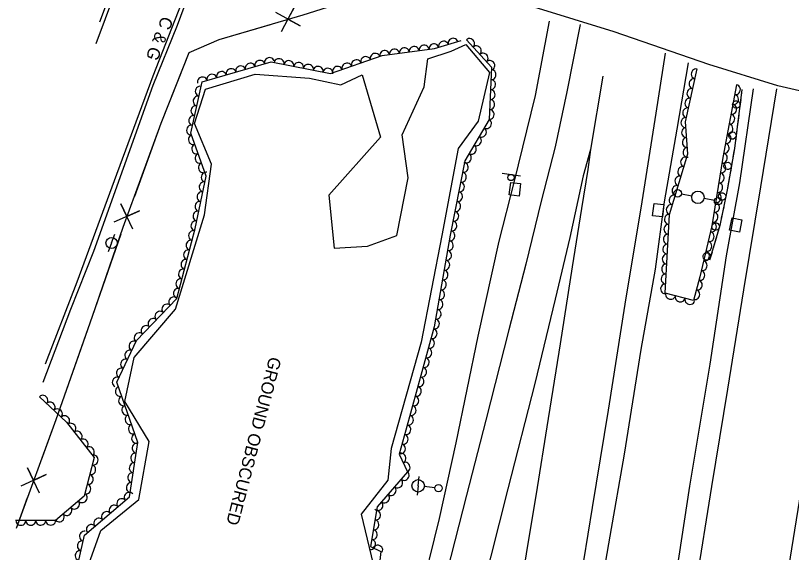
# Model space of a CAD drawing. Extents: x 1722896 to 1754269, y 648279 to 666297.
# Drawn here: x 1725426.2 to 1725737.8, y 659590.4 to 659806.2 of the extents above; entities that cross this region are included whole.
import ezdxf

# ---------------------------------------------------------------- set-up
doc = ezdxf.new("R2010")
doc.units = 0
for name, color, linetype in [('DESIGN - CENTERLINE - Proposed', 7, 'Continuous'), ('DESIGN - CENTERLINE - Proposed Text', 7, 'Continuous'), ('DESIGN - PUBLIC HEARING - Shapes', 7, 'Continuous'), ('DESIGN - SCRATCH - User 1', 7, 'Continuous'), ('SURVEY - CENTERLINE - Preliminary', 7, 'Continuous'), ('SURVEY - CENTERLINE - Preliminary Text', 7, 'Continuous'), ('SURVEY - DRAINAGE - Natural Features', 7, 'Continuous'), ('SURVEY - DTM - Breaklines', 7, 'Continuous'), ('SURVEY - VEGETATION - Features with Text', 7, 'Continuous')]:
    doc.layers.add(name, color=color, linetype=linetype)

msp = doc.modelspace()

# ---------------------------------------------------------------- linework, layer by layer
at = {"layer": 'DESIGN - CENTERLINE - Proposed'}
msp.add_lwpolyline([(1725873.4, 659822.69), (1725871.84, 659814.34), (1725866.25, 659775.49), (1725864.61, 659769.04), (1725840.89, 659767.23), (1725811.36, 659766.56), (1725786.34, 659767.74), (1725753.72, 659772.97), (1725732.26, 659777.9), (1725704.65, 659786.55), (1725666.54, 659799.64), (1725616.61, 659815.21), (1725586.06, 659824.9), (1725587.44, 659831.41), (1725593.62, 659870.36), (1725595.34, 659877.02)], dxfattribs=at)
at = {"layer": 'DESIGN - CENTERLINE - Proposed Text'}
for points in [[(1725591.57, 659822.25), (1725541.53, 659806.35), (1725507.88, 659796.45), (1725495.73, 659791.23), (1725484.59, 659762.77), (1725469.34, 659721.04), (1725456.93, 659685.27), (1725442.38, 659643.72), (1725426.43, 659600.07)], [(1725532.95, 659799.76), (1725538.27, 659809.67), (1725535.56, 659804.7), (1725540.53, 659801.99), (1725530.69, 659807.44)], [(1725528.49, 659802.52), (1725507.88, 659796.45), (1725495.73, 659791.23), (1725491.47, 659780.35)], [(1725491.47, 659780.35), (1725484.59, 659762.77), (1725473.91, 659733.54)], [(1725473.25, 659720.36), (1725468.44, 659730.53), (1725470.83, 659725.4), (1725475.96, 659727.78), (1725465.73, 659723.11)], [(1725468.43, 659718.4), (1725456.93, 659685.27), (1725453.18, 659674.58)], [(1725453.18, 659674.58), (1725442.38, 659643.72), (1725436.44, 659627.46)], [(1725435.77, 659614.29), (1725430.97, 659624.46), (1725433.35, 659619.33), (1725438.49, 659621.71), (1725428.26, 659617.04)], [(1725430.91, 659612.34), (1725426.43, 659600.07)]]:
    msp.add_lwpolyline(points, dxfattribs=at)
at = {"layer": 'DESIGN - PUBLIC HEARING - Shapes'}
msp.add_line((1725621.62, 659742.89), (1725629.03, 659741.74), dxfattribs=at)
msp.add_circle((1725625.16, 659741.1), 1.25, dxfattribs=at)
at = {"layer": 'DESIGN - SCRATCH - User 1'}
for points in [[(1725717.91, 659776.41), (1725714.9, 659752.76), (1725712.14, 659736.83), (1725709.02, 659721.78), (1725704.91, 659707.83)], [(1725717.91, 659776.41), (1725717.61, 659774.08)], [(1725717.41, 659772.49), (1725716.83, 659767.93)], [(1725716.33, 659764.01), (1725716.04, 659761.68)], [(1725716.63, 659766.34), (1725716.33, 659764.01)], [(1725715.83, 659760.09), (1725715.26, 659755.53)], [(1725714.71, 659751.62), (1725714.3, 659749.3)], [(1725715.05, 659753.94), (1725714.9, 659752.76), (1725714.71, 659751.62)], [(1725714.03, 659747.73), (1725713.25, 659743.19)], [(1725712.57, 659739.3), (1725712.17, 659736.99)], [(1725712.97, 659741.62), (1725712.57, 659739.3)], [(1725711.85, 659735.42), (1725710.91, 659730.92)], [(1725710.11, 659727.05), (1725709.63, 659724.75)], [(1725710.59, 659729.35), (1725710.11, 659727.05)], [(1725709.31, 659723.18), (1725709.02, 659721.78), (1725708.12, 659718.74)], [(1725707.67, 659717.2), (1725707.01, 659714.95)], [(1725707.01, 659714.95), (1725706.34, 659712.7)], [(1725705.89, 659711.16), (1725704.91, 659707.83)]]:
    msp.add_lwpolyline(points, dxfattribs=at)
for centre, start, end in [((1725715.64, 659770.42), 106.0198, 106.0099), ((1725714.06, 659758.02), 106.0198, 106.0099), ((1725712.16, 659745.74), 103.4291, 103.4193), ((1725709.92, 659733.49), 101.5223, 101.5124), ((1725707.34, 659721.39), 96.8781, 96.8683), ((1725703.81, 659709.4), 96.8781, 96.8683)]:
    msp.add_arc(centre, 1.5, start, end, dxfattribs=at)
at = {"layer": 'SURVEY - CENTERLINE - Preliminary'}
for points in [[(1725452.97, 659578.29), (1725460.4, 659599.26), (1725475.66, 659611.68), (1725479.85, 659635.04), (1725470.12, 659651.09), (1725473.88, 659668.78), (1725490.45, 659688.16), (1725502.05, 659726.06), (1725504.83, 659746.44), (1725498.09, 659762.81), (1725502.49, 659776.59), (1725522.38, 659782.63), (1725544.18, 659780.97), (1725556.82, 659778.3), (1725565.39, 659782.42), (1725572.7, 659757.38), (1725552.02, 659734.04), (1725554.2, 659712.66), (1725567.55, 659713.46), (1725579.38, 659717.85), (1725583.9, 659740.93), (1725581.42, 659758.21), (1725590.29, 659777.53), (1725591.79, 659788.8), (1725601.15, 659791.84), (1725607, 659794.61)], [(1725607, 659794.61), (1725616.48, 659783.36), (1725612, 659763.76), (1725603.94, 659752.8), (1725597.41, 659717.82), (1725589.03, 659674.93), (1725577.08, 659632.19), (1725575.73, 659619.48), (1725565.06, 659605.84), (1725569.84, 659585.79)]]:
    msp.add_lwpolyline(points, dxfattribs=at)
at = {"layer": 'SURVEY - CENTERLINE - Preliminary Text'}
for points in [[(1725475.25, 659877.21), (1725479.16, 659873.75), (1725481.44, 659870.6), (1725483.2, 659865.75), (1725483.33, 659861.83), (1725482.61, 659857.42), (1725479.69, 659850.19), (1725472.45, 659831.99), (1725465.99, 659815.01), (1725458.48, 659794.83)], [(1725474.48, 659875.7), (1725477.04, 659873.79), (1725479.42, 659871.22), (1725480.89, 659868.09), (1725481.79, 659863.63), (1725481.25, 659857.67), (1725476.85, 659847.43), (1725468.91, 659827.5), (1725459.9, 659803.51)], [(1725586.72, 659832.95), (1725561.03, 659841.8), (1725539.85, 659849.35), (1725530.51, 659852.94), (1725525.68, 659854.1), (1725520.16, 659853.9), (1725514.36, 659852.01), (1725509.77, 659849.09), (1725506.48, 659845.71), (1725502.63, 659838.48), (1725492.72, 659810.96), (1725481.27, 659781.84), (1725465.74, 659739.73), (1725450.86, 659699.09), (1725438.04, 659666.13)], [(1725586.35, 659831.55), (1725556.04, 659841.25), (1725547.17, 659844.96), (1725537.97, 659848.28), (1725529.75, 659851.86), (1725524.54, 659852.8), (1725518.49, 659852.08), (1725513.81, 659849.69), (1725509.63, 659846.2), (1725506.42, 659842.05), (1725504.57, 659838.39), (1725499.07, 659824.01), (1725491.15, 659802.17), (1725481.36, 659778.09), (1725457.53, 659711.43), (1725448.22, 659688.09), (1725437.21, 659658.73)], [(1725652.91, 659802.61), (1725647.58, 659775.59), (1725642.85, 659753.38), (1725637.33, 659731.58), (1725631.16, 659706.25), (1725624.23, 659679.85), (1725615.03, 659643.61), (1725607.34, 659613.41), (1725597.89, 659576.72), (1725589.06, 659541.14), (1725578.75, 659500.08), (1725567.43, 659455.03), (1725559.55, 659424.16), (1725549.03, 659384.34), (1725539.14, 659344.25), (1725529.13, 659305.07), (1725518.6, 659263.2), (1725508.75, 659224.8), (1725496.9, 659177.81)], [(1725640.49, 659803.97), (1725634.81, 659774.04), (1725626.25, 659739.06), (1725620.32, 659715.48), (1725611.78, 659677.37)], [(1725687.08, 659791.05), (1725683.3, 659766.93), (1725677.71, 659731.3), (1725670.86, 659690.25), (1725664.14, 659647.62), (1725657.77, 659608.5), (1725652.59, 659576.32), (1725647.81, 659547.04), (1725643.39, 659519.4), (1725637.87, 659485.77), (1725633.69, 659458.14), (1725628.22, 659425.7), (1725623, 659391.41), (1725617.73, 659354.38), (1725611.5, 659311.51), (1725607.19, 659278.21), (1725602.12, 659236.1), (1725597.31, 659189.41)], [(1725696.29, 659787.13), (1725691.73, 659760.59), (1725686.73, 659731.33), (1725683.03, 659704.34), (1725677.35, 659671.94), (1725670.56, 659629.98), (1725664.9, 659597.03), (1725657.75, 659555.96), (1725650.57, 659508.89), (1725645.1, 659474.58), (1725638.66, 659436.1), (1725630.35, 659380.46), (1725623.94, 659338.73), (1725619.64, 659306.89), (1725613.47, 659259.3), (1725607.99, 659209.36)], [(1725661.98, 659781.81), (1725657.04, 659752.42), (1725655.96, 659744.32), (1725653.54, 659728.68), (1725649.76, 659705.24), (1725644.88, 659674.27), (1725639.6, 659640.89), (1725635.71, 659616.55), (1725631.26, 659589.89), (1725627.76, 659567.71), (1725621.91, 659530.77), (1725614.26, 659484.48), (1725606.79, 659435.71), (1725599.35, 659388.68), (1725592.61, 659343.39), (1725588.38, 659312.53), (1725582.2, 659264.97), (1725577.11, 659220.19), (1725572.73, 659177.83)], [(1725722.48, 659776.73), (1725716.86, 659738.92), (1725711.6, 659709.57), (1725705.06, 659666.07), (1725696.9, 659617.11), (1725688.33, 659560.79), (1725680.48, 659512.54), (1725674.79, 659476.13), (1725671.39, 659452.68), (1725663.47, 659403.29), (1725656.9, 659362.38), (1725650.62, 659318.57), (1725644.02, 659268.92), (1725637.59, 659216.78), (1725635.42, 659193.16)], [(1725731.83, 659776.73), (1725725.33, 659737.39), (1725718.54, 659695.92), (1725712.05, 659656.08), (1725705.74, 659616.91), (1725699.42, 659577.61), (1725692.98, 659536.68), (1725687.06, 659498.6), (1725681.09, 659460.02), (1725674.91, 659421.32), (1725668.06, 659377.79), (1725661.5, 659334.78), (1725654.91, 659286), (1725649.25, 659240.38), (1725644.65, 659197.9)], [(1725766.06, 659769.03), (1725761.17, 659736.93), (1725754.55, 659696.19), (1725749.3, 659664.3), (1725742.73, 659622.71), (1725736.63, 659584.4), (1725730.48, 659544.9), (1725724.69, 659509.09), (1725719.31, 659474.94), (1725713.29, 659436.1)], [(1725657.04, 659752.42), (1725654.13, 659741.72), (1725648.74, 659716.98), (1725642.96, 659692.25), (1725634.79, 659658.33), (1725623.89, 659616.06), (1725613.54, 659575.17), (1725605.44, 659543.5), (1725597.06, 659510.14), (1725585.35, 659464.48), (1725575.97, 659426.58), (1725564.77, 659382.92), (1725557.3, 659352.79), (1725545.54, 659307.31), (1725533.43, 659259.44), (1725519.79, 659205.83)], [(1725611.78, 659677.37), (1725602.98, 659634.55), (1725596.27, 659604.09), (1725588.17, 659570.84), (1725575.5, 659522.84), (1725566.76, 659487.81), (1725556.97, 659445.34), (1725545.28, 659400.08), (1725534.58, 659360.94), (1725525.24, 659323.16), (1725515.51, 659283.86), (1725504.17, 659240.72), (1725493.79, 659199.26)]]:
    msp.add_lwpolyline(points, dxfattribs=at)
at = {"layer": 'SURVEY - DRAINAGE - Natural Features'}
for p, q in [((1725626.74, 659736.38), (1725626.74, 659736.38)), ((1725684.31, 659727.97), (1725684.31, 659727.97)), ((1725715.4, 659722.01), (1725715.4, 659722.01))]:
    msp.add_line(p, q, dxfattribs=at)
for points in [[(1725625.04, 659739.09), (1725629.01, 659738.64), (1725628.44, 659733.67), (1725624.47, 659734.13), (1725625.04, 659739.09)], [(1725682.63, 659730.7), (1725686.6, 659730.2), (1725685.98, 659725.24), (1725682.02, 659725.74), (1725682.63, 659730.7)], [(1725713.93, 659724.85), (1725717.85, 659724.07), (1725716.87, 659719.16), (1725712.95, 659719.95), (1725713.93, 659724.85)]]:
    msp.add_lwpolyline(points, dxfattribs=at)
at = {"layer": 'SURVEY - DTM - Breaklines'}
for p, q in [((1725697.77, 659733.64), (1725693.6, 659734.46)), ((1725706.85, 659731.86), (1725702.68, 659732.68)), ((1725464.75, 659714.8), (1725466.09, 659718.3)), ((1725464.75, 659714.8), (1725463.41, 659711.29)), ((1725587.88, 659617.23), (1725588.32, 659620.95)), ((1725587.88, 659617.23), (1725587.44, 659613.51)), ((1725594.59, 659616.44), (1725590.36, 659616.94))]:
    msp.add_line(p, q, dxfattribs=at)
for centre, radius in [((1725692.13, 659734.74), 1.5), ((1725700.23, 659733.16), 2.5), ((1725708.32, 659731.58), 1.5), ((1725464.75, 659714.8), 2.25), ((1725587.88, 659617.23), 2.5), ((1725596.07, 659616.26), 1.5)]:
    msp.add_circle(centre, radius, dxfattribs=at)
at = {"layer": 'SURVEY - VEGETATION - Features with Text'}
for points in [[(1725449.12, 659576.07), (1725453.87, 659597.42), (1725472.01, 659612.85), (1725475.28, 659634.6), (1725466.89, 659658.85), (1725474.72, 659675.67), (1725490.94, 659692.49), (1725498.33, 659720.66), (1725502.73, 659741.67), (1725496.54, 659758.99), (1725501.12, 659779.56), (1725528.86, 659787.6), (1725552.72, 659782.92), (1725573.48, 659790.11), (1725594.49, 659792.93), (1725605.1, 659796.13)], [(1725607.23, 659796.46), (1725617.39, 659785.46), (1725616.43, 659764.47), (1725606.6, 659747.78), (1725600.79, 659717.88), (1725594.31, 659681.12), (1725582.99, 659639.53), (1725580.28, 659629.97), (1725583.59, 659622.79), (1725571.42, 659608.8), (1725568.79, 659592.84), (1725572.9, 659590.88), (1725571.4, 659577.57)], [(1725715.77, 659778.36), (1725710.2, 659749.2), (1725705.84, 659721.66), (1725700.96, 659701.26), (1725698.4, 659691.62), (1725687.03, 659694.63), (1725688.8, 659726.22), (1725696.17, 659750.62), (1725695.25, 659763.52), (1725699.88, 659784.83)], [(1725435.77, 659653.03), (1725446.64, 659642.79), (1725457.73, 659628.59), (1725453.76, 659613.01), (1725442.26, 659603.33), (1725426.19, 659603.22)]]:
    msp.add_lwpolyline(points, dxfattribs=at)
for centre, major_axis in [((1725594.24, 659792.9), (1.98, 0.27)), ((1725598.08, 659794.01), (1.91, 0.58)), ((1725601.91, 659795.17), (1.91, 0.58)), ((1725608.59, 659794.99), (1.36, -1.47)), ((1725574.42, 659790.24), (1.98, 0.27)), ((1725578.38, 659790.77), (1.98, 0.27)), ((1725582.35, 659791.3), (1.98, 0.27)), ((1725586.31, 659791.84), (1.98, 0.27)), ((1725590.27, 659792.37), (1.98, 0.27)), ((1725611.3, 659792.05), (1.36, -1.47)), ((1725528.12, 659787.38), (1.92, 0.56)), ((1725532.03, 659786.98), (1.96, -0.38)), ((1725563.03, 659786.5), (1.89, 0.65)), ((1725566.81, 659787.8), (1.89, 0.65)), ((1725570.59, 659789.11), (1.89, 0.65)), ((1725614.02, 659789.11), (1.36, -1.47)), ((1725516.59, 659784.04), (1.92, 0.56)), ((1725520.44, 659785.16), (1.92, 0.56)), ((1725524.28, 659786.27), (1.92, 0.56)), ((1725535.95, 659786.21), (1.96, -0.38)), ((1725539.88, 659785.44), (1.96, -0.38)), ((1725543.8, 659784.67), (1.96, -0.38)), ((1725547.73, 659783.9), (1.96, -0.38)), ((1725555.47, 659783.88), (1.89, 0.65)), ((1725559.25, 659785.19), (1.89, 0.65)), ((1725616.73, 659786.17), (1.36, -1.47)), ((1725505.07, 659780.7), (1.92, 0.56)), ((1725508.91, 659781.81), (1.92, 0.56)), ((1725512.75, 659782.93), (1.92, 0.56)), ((1725551.66, 659783.13), (1.96, -0.38)), ((1725617.25, 659782.43), (-0.09, -2)), ((1725699.42, 659782.73), (0.42, 1.95)), ((1725501.23, 659779.59), (1.92, 0.56)), ((1725617.07, 659778.44), (-0.09, -2)), ((1725698.57, 659778.82), (0.42, 1.95)), ((1725500.28, 659775.76), (0.44, 1.95)), ((1725616.89, 659774.44), (-0.09, -2)), ((1725697.72, 659774.91), (0.42, 1.95)), ((1725715.4, 659776.4), (-0.38, -1.96)), ((1725499.41, 659771.85), (0.44, 1.95)), ((1725696.88, 659771), (0.42, 1.95)), ((1725714.65, 659772.47), (-0.38, -1.96)), ((1725498.54, 659767.95), (0.44, 1.95)), ((1725616.7, 659770.45), (-0.09, -2)), ((1725713.89, 659768.54), (-0.38, -1.96)), ((1725616.52, 659766.45), (-0.09, -2)), ((1725696.03, 659767.09), (0.42, 1.95)), ((1725497.66, 659764.04), (0.44, 1.95)), ((1725615.41, 659762.73), (-1.02, -1.72)), ((1725695.28, 659763.18), (-0.14, 1.99)), ((1725713.14, 659764.61), (-0.38, -1.96)), ((1725496.79, 659760.14), (0.44, 1.95)), ((1725613.38, 659759.29), (-1.02, -1.72)), ((1725695.56, 659759.19), (-0.14, 1.99)), ((1725712.39, 659760.68), (-0.38, -1.96)), ((1725497.49, 659756.33), (-0.67, 1.88)), ((1725611.35, 659755.84), (-1.02, -1.72)), ((1725711.64, 659756.75), (-0.38, -1.96)), ((1725498.84, 659752.57), (-0.67, 1.88)), ((1725695.84, 659755.2), (-0.14, 1.99)), ((1725710.89, 659752.82), (-0.38, -1.96)), ((1725609.32, 659752.39), (-1.02, -1.72)), ((1725696.13, 659751.21), (-0.14, 1.99)), ((1725500.18, 659748.8), (-0.67, 1.88)), ((1725607.28, 659748.95), (-1.02, -1.72)), ((1725695.18, 659747.35), (0.58, 1.91)), ((1725710.15, 659748.89), (-0.31, -1.98)), ((1725501.53, 659745.03), (-0.67, 1.88)), ((1725606.09, 659745.19), (-0.38, -1.96)), ((1725694.03, 659743.53), (0.58, 1.91)), ((1725709.52, 659744.94), (-0.31, -1.98)), ((1725502.65, 659741.25), (0.41, 1.96)), ((1725605.33, 659741.26), (-0.38, -1.96)), ((1725692.87, 659739.7), (0.58, 1.91)), ((1725708.9, 659740.99), (-0.31, -1.98)), ((1725501.82, 659737.34), (0.41, 1.96)), ((1725604.57, 659737.33), (-0.38, -1.96)), ((1725708.27, 659737.04), (-0.31, -1.98)), ((1725691.71, 659735.87), (0.58, 1.91)), ((1725501, 659733.42), (0.41, 1.96)), ((1725603.8, 659733.41), (-0.38, -1.96)), ((1725690.56, 659732.04), (0.58, 1.91)), ((1725707.65, 659733.09), (-0.31, -1.98)), ((1725500.18, 659729.51), (0.41, 1.96)), ((1725603.04, 659729.48), (-0.38, -1.96)), ((1725689.4, 659728.21), (0.58, 1.91)), ((1725707.02, 659729.14), (-0.31, -1.98)), ((1725499.36, 659725.59), (0.41, 1.96)), ((1725602.28, 659725.55), (-0.38, -1.96)), ((1725688.69, 659724.3), (0.11, 2)), ((1725706.4, 659725.19), (-0.31, -1.98)), ((1725498.54, 659721.68), (0.41, 1.96)), ((1725601.52, 659721.63), (-0.38, -1.96)), ((1725705.74, 659721.24), (-0.47, -1.95)), ((1725688.47, 659720.31), (0.11, 2)), ((1725497.58, 659717.8), (0.51, 1.93)), ((1725600.76, 659717.7), (-0.35, -1.97)), ((1725688.25, 659716.31), (0.11, 2)), ((1725704.81, 659717.35), (-0.47, -1.95)), ((1725496.56, 659713.93), (0.51, 1.93)), ((1725600.06, 659713.76), (-0.35, -1.97)), ((1725688.02, 659712.32), (0.11, 2)), ((1725703.88, 659713.46), (-0.47, -1.95)), ((1725495.55, 659710.06), (0.51, 1.93)), ((1725599.37, 659709.82), (-0.35, -1.97)), ((1725702.95, 659709.57), (-0.47, -1.95)), ((1725494.53, 659706.19), (0.51, 1.93)), ((1725598.67, 659705.88), (-0.35, -1.97)), ((1725687.8, 659708.32), (0.11, 2)), ((1725702.02, 659705.68), (-0.47, -1.95)), ((1725493.52, 659702.32), (0.51, 1.93)), ((1725687.57, 659704.33), (0.11, 2)), ((1725597.98, 659701.94), (-0.35, -1.97)), ((1725687.35, 659700.34), (0.11, 2)), ((1725701.09, 659701.79), (-0.47, -1.95)), ((1725492.5, 659698.45), (0.51, 1.93)), ((1725597.29, 659698), (-0.35, -1.97)), ((1725687.13, 659696.34), (0.11, 2)), ((1725700.08, 659697.92), (-0.51, -1.93)), ((1725491.49, 659694.58), (0.51, 1.93)), ((1725596.59, 659694.06), (-0.35, -1.97)), ((1725699.05, 659694.06), (-0.51, -1.93)), ((1725489.67, 659691.17), (1.39, 1.44)), ((1725595.9, 659690.12), (-0.35, -1.97)), ((1725689.24, 659694.05), (-1.93, 0.51)), ((1725693.11, 659693.02), (-1.93, 0.51)), ((1725696.97, 659692), (-1.93, 0.51)), ((1725486.89, 659688.29), (1.39, 1.44)), ((1725484.11, 659685.41), (1.39, 1.44)), ((1725595.21, 659686.18), (-0.35, -1.97)), ((1725481.34, 659682.53), (1.39, 1.44)), ((1725594.51, 659682.24), (-0.35, -1.97)), ((1725478.56, 659679.65), (1.39, 1.44)), ((1725593.56, 659678.36), (-0.53, -1.93)), ((1725475.78, 659676.77), (1.39, 1.44)), ((1725592.51, 659674.5), (-0.53, -1.93)), ((1725473.68, 659673.43), (0.84, 1.81)), ((1725471.99, 659669.8), (0.84, 1.81)), ((1725591.46, 659670.64), (-0.53, -1.93)), ((1725470.3, 659666.18), (0.84, 1.81)), ((1725590.41, 659666.78), (-0.53, -1.93)), ((1725468.62, 659662.55), (0.84, 1.81)), ((1725589.36, 659662.92), (-0.53, -1.93)), ((1725466.93, 659658.92), (0.84, 1.81)), ((1725588.31, 659659.07), (-0.53, -1.93)), ((1725468.18, 659655.15), (-0.65, 1.89)), ((1725587.25, 659655.21), (-0.53, -1.93)), ((1725437.23, 659651.66), (1.46, -1.37)), ((1725469.48, 659651.37), (-0.65, 1.89)), ((1725586.2, 659651.35), (-0.53, -1.93)), ((1725440.14, 659648.92), (1.46, -1.37)), ((1725470.79, 659647.59), (-0.65, 1.89)), ((1725585.15, 659647.49), (-0.53, -1.93)), ((1725443.05, 659646.18), (1.46, -1.37)), ((1725445.96, 659643.43), (1.46, -1.37)), ((1725472.1, 659643.81), (-0.65, 1.89)), ((1725584.1, 659643.63), (-0.53, -1.93)), ((1725448.53, 659640.38), (1.23, -1.58)), ((1725450.99, 659637.22), (1.23, -1.58)), ((1725473.41, 659640.03), (-0.65, 1.89)), ((1725583.05, 659639.77), (-0.53, -1.93)), ((1725453.45, 659634.07), (1.23, -1.58)), ((1725474.71, 659636.25), (-0.65, 1.89)), ((1725581.96, 659635.92), (-0.54, -1.92)), ((1725455.91, 659630.92), (1.23, -1.58)), ((1725474.95, 659632.37), (0.3, 1.98)), ((1725580.87, 659632.07), (-0.54, -1.92)), ((1725474.35, 659628.41), (0.3, 1.98)), ((1725581.04, 659628.32), (0.84, -1.82)), ((1725457.47, 659627.57), (-0.49, -1.94)), ((1725473.76, 659624.46), (0.3, 1.98)), ((1725582.72, 659624.69), (0.84, -1.82)), ((1725456.48, 659623.7), (-0.49, -1.94)), ((1725455.5, 659619.82), (-0.49, -1.94)), ((1725473.16, 659620.5), (0.3, 1.98)), ((1725582.34, 659621.35), (-1.31, -1.51)), ((1725454.51, 659615.94), (-0.49, -1.94)), ((1725472.57, 659616.55), (0.3, 1.98)), ((1725579.71, 659618.33), (-1.31, -1.51)), ((1725471.81, 659612.68), (1.52, 1.3)), ((1725577.09, 659615.31), (-1.31, -1.51)), ((1725449.96, 659609.81), (-1.53, -1.29)), ((1725453.02, 659612.38), (-1.53, -1.29)), ((1725468.76, 659610.09), (1.52, 1.3)), ((1725574.46, 659612.3), (-1.31, -1.51)), ((1725446.9, 659607.23), (-1.53, -1.29)), ((1725465.72, 659607.5), (1.52, 1.3)), ((1725571.83, 659609.28), (-1.31, -1.51)), ((1725443.84, 659604.66), (-1.53, -1.29)), ((1725462.67, 659604.91), (1.52, 1.3)), ((1725570.87, 659605.48), (-0.33, -1.97)), ((1725428.32, 659603.23), (-2, -0.01)), ((1725432.32, 659603.26), (-2, -0.01)), ((1725436.32, 659603.29), (-2, -0.01)), ((1725440.32, 659603.32), (-2, -0.01)), ((1725456.57, 659599.72), (1.52, 1.3)), ((1725459.62, 659602.31), (1.52, 1.3)), ((1725570.22, 659601.53), (-0.33, -1.97)), ((1725453.77, 659596.98), (0.43, 1.95)), ((1725569.57, 659597.59), (-0.33, -1.97)), ((1725568.92, 659593.64), (-0.33, -1.97)), ((1725452.9, 659593.08), (0.43, 1.95)), ((1725571.67, 659591.47), (1.8, -0.86)), ((1725452.04, 659589.17), (0.43, 1.95))]:
    msp.add_ellipse(centre, major_axis=major_axis, ratio=0.940188, start_param=0, end_param=3.141593, dxfattribs=at)

# ---------------------------------------------------------------- texts
at = {"layer": 'DESIGN - SCRATCH - User 1'}
msp.add_text('C & G', height=5, rotation=248.5512, dxfattribs=at).set_placement((1725485.05, 659806.24))
at = {"layer": 'SURVEY - CENTERLINE - Preliminary'}
msp.add_text('GROUND OBSCURED', height=5, rotation=255.4388, dxfattribs=at).set_placement((1725528.18, 659669.37))

doc.saveas('drawing.dxf')
